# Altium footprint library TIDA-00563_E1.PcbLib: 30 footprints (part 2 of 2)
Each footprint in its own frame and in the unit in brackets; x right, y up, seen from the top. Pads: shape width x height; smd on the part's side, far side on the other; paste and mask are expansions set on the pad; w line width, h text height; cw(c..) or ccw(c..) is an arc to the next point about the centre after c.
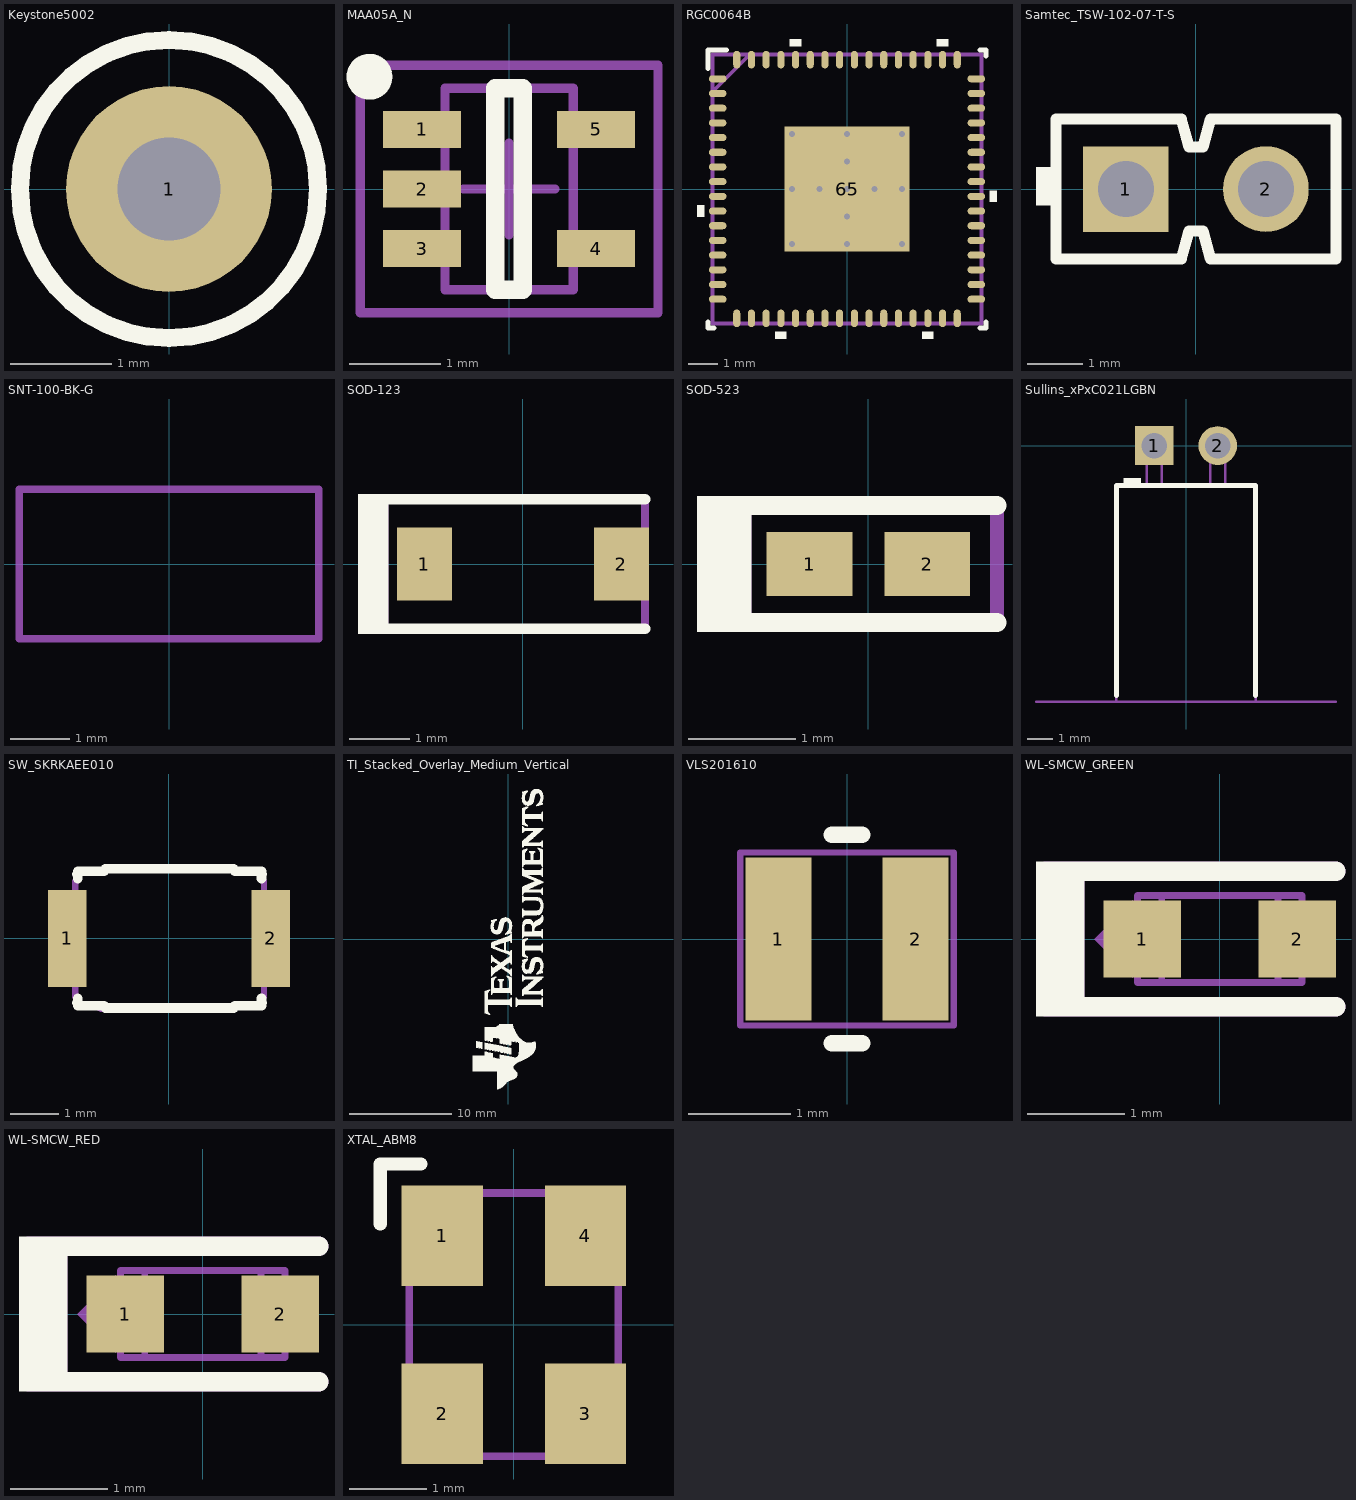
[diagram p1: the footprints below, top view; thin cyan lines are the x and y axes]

## Keystone5002 [mil] "For Keystone 500x miniature loop terminals"
height 181.1
pads (1):
  round 80 hole 40: 1(0,0)
Top Overlay:
  circle w7: c0,0 r58
Mechanical 5:
  circle w5: c0,0 r58.31
  text ".Designator" at -45,-10 h25
3D body: height 181.97, standoff -118.11, extent -49,-49 49.04,49.23

## MAA05A_N [mm] "SOT353, 5-Leads, Body 2x1.3mm, Pitch 0.65mm, Lead Span 2.1mm, IPC Medium Density"
height 1.1
pads (5):
  rect 0.85x0.4 smd: 1(-0.95,0.65) 2(-0.95,0) 3(-0.95,-0.65) 4(0.95,-0.65) 5(0.95,0.65)
Top Overlay:
  circle w0.25: c-1.524,1.225 r0.125
  lines w0.2: -0.15,-1.1 -0.15,1.1 0.15,1.1 0.15,-1.1 -0.15,-1.1
Mechanical 5:
  lines w0.1: -0.7,-1.1 -0.7,1.1 0.7,1.1 0.7,-1.1 -0.7,-1.1
  text ".Designator" at 0.33,-0.432 h0.64
Mechanical 15:
  lines w0.1: -0.5,0 0.5,0 ; 0,-0.5 0,0.5 ; -1.625,-1.35 1.625,-1.35 1.625,1.35 -1.625,1.35 -1.625,-1.35
3D body: height 1.1, standoff 0, extent -0.7,-1.1 0.7,1.1

## RGC0064B [mm]
height 1
pads (65):
  oval 0.6x0.24 smd mask+0.07: 1(-4.4,3.75) 2(-4.4,3.25) 3(-4.4,2.75) 4(-4.4,2.25) 5(-4.4,1.75) 6(-4.4,1.25) 7(-4.4,0.75) 8(-4.4,0.25) 9(-4.4,-0.25) 10(-4.4,-0.75) 11(-4.4,-1.25) 12(-4.4,-1.75) 13(-4.4,-2.25) 14(-4.4,-2.75) 15(-4.4,-3.25) 16(-4.4,-3.75) 33(4.4,-3.75) 34(4.4,-3.25) 35(4.4,-2.75) 36(4.4,-2.25) 37(4.4,-1.75) 38(4.4,-1.25) 39(4.4,-0.75) 40(4.4,-0.25) 41(4.4,0.25) 42(4.4,0.75) 43(4.4,1.25) 44(4.4,1.75) 45(4.4,2.25) 46(4.4,2.75) 47(4.4,3.25) 48(4.4,3.75)
  oval 0.24x0.6 smd mask+0.07: 17(-3.751,-4.4) 18(-3.251,-4.4) 19(-2.751,-4.4) 20(-2.251,-4.4) 21(-1.75,-4.4) 22(-1.25,-4.4) 23(-0.75,-4.4) 24(-0.25,-4.4) 25(0.25,-4.4) 26(0.75,-4.4) 27(1.25,-4.4) 28(1.75,-4.4) 29(2.251,-4.4) 30(2.751,-4.4) 31(3.251,-4.4) 32(3.751,-4.4) 49(3.751,4.4) 50(3.251,4.4) 51(2.751,4.4) 52(2.251,4.4) 53(1.75,4.4) 54(1.25,4.4) 55(0.75,4.4) 56(0.25,4.4) 57(-0.25,4.4) 58(-0.75,4.4) 59(-1.25,4.4) 60(-1.75,4.4) 61(-2.251,4.4) 62(-2.751,4.4) 63(-3.251,4.4) 64(-3.751,4.4)
  rect 4.25x4.25 smd paste-2.112: 65(0,0)
via -1.875,1.875 diameter 0.5 hole 0.2
via 0,1.875 diameter 0.5 hole 0.2
via 1.875,1.875 diameter 0.5 hole 0.2
via 0,0.937 diameter 0.5 hole 0.2
via -1.875,0 diameter 0.5 hole 0.2
via -0.937,0 diameter 0.5 hole 0.2
via 0,0 diameter 0.5 hole 0.2
via 0.937,0 diameter 0.5 hole 0.2
via 1.875,0 diameter 0.5 hole 0.2
via 0,-0.937 diameter 0.5 hole 0.2
via -1.875,-1.875 diameter 0.5 hole 0.2
via 0,-1.875 diameter 0.5 hole 0.2
via 1.875,-1.875 diameter 0.5 hole 0.2
Top Overlay:
  region: -4.849,-0.56 -5.103,-0.56 -5.103,-0.941 -4.849,-0.941
  region: -2.06,-4.849 -2.441,-4.849 -2.441,-5.103 -2.06,-5.103
  region: 2.941,-4.849 2.56,-4.849 2.56,-5.103 2.941,-5.103
  region: 4.849,-0.059 5.103,-0.059 5.103,-0.44 4.849,-0.44
  region: 3.441,4.849 3.06,4.849 3.06,5.103 3.441,5.103
  region: -1.56,4.849 -1.941,4.849 -1.941,5.103 -1.56,5.103
  lines w0.178: -4.725,-4.525 -4.725,-4.725 -4.525,-4.725 ; -4.725,4.096 -4.725,4.725 -4.097,4.725 ; 4.525,-4.725 4.725,-4.725 4.725,-4.525 ; 4.525,4.725 4.725,4.725 4.725,4.525
Top Paste:
  rectangle: 0.1,-1.888 1.888,-0.1
  region: -0.1,-0.1 -1.888,-0.1 -1.888,-1.888 -0.1,-1.888
  region: -0.1,1.888 -1.888,1.888 -1.888,0.1 -0.1,0.1
  rectangle: 0.1,0.1 1.888,1.888
Mechanical 5:
  lines w0.127: -4.575,3.305 -3.305,4.575 ; -4.575,-4.575 4.575,-4.575 4.575,4.575 -4.575,4.575 -4.575,-4.575 ; -4.575,-3.9 -4.575,-3.6 -4.575,-3.9 ; -4.575,-3.4 -4.575,-3.1 -4.575,-3.4 ; -4.575,-2.9 -4.575,-2.6 -4.575,-2.9 ; -4.575,-2.4 -4.575,-2.1 -4.575,-2.4 ; -4.575,-1.9 -4.575,-1.6 -4.575,-1.9 ; -4.575,-1.4 -4.575,-1.1 -4.575,-1.4 ; -4.575,-0.9 -4.575,-0.6 -4.575,-0.9 ; -4.575,-0.4 -4.575,-0.1 -4.575,-0.4 ; -4.575,0.1 -4.575,0.4 -4.575,0.1 ; -4.575,0.6 -4.575,0.9 -4.575,0.6 ; -4.575,1.1 -4.575,1.4 -4.575,1.1 ; -4.575,1.6 -4.575,1.9 -4.575,1.6 ; -4.575,2.1 -4.575,2.4 -4.575,2.1 ; -4.575,2.6 -4.575,2.9 -4.575,2.6 ; -4.575,3.1 -4.575,3.4 -4.575,3.1 ; -4.575,3.6 -4.575,3.9 -4.575,3.6 ; -3.9,-4.575 -3.6,-4.575 -3.9,-4.575 ; -3.9,4.575 -3.6,4.575 -3.9,4.575 ; -3.4,-4.575 -3.1,-4.575 -3.4,-4.575 ; -3.4,4.575 -3.1,4.575 -3.4,4.575 ; -2.9,-4.575 -2.6,-4.575 -2.9,-4.575 ; -2.9,4.575 -2.6,4.575 -2.9,4.575 ; -2.4,-4.575 -2.1,-4.575 -2.4,-4.575 ; -2.4,4.575 -2.1,4.575 -2.4,4.575 ; -1.9,-4.575 -1.6,-4.575 -1.9,-4.575 ; -1.9,4.575 -1.6,4.575 -1.9,4.575 ; -1.4,-4.575 -1.1,-4.575 -1.4,-4.575 ; -1.4,4.575 -1.1,4.575 -1.4,4.575 ; -0.9,-4.575 -0.6,-4.575 -0.9,-4.575 ; -0.9,4.575 -0.6,4.575 -0.9,4.575 ; -0.4,-4.575 -0.1,-4.575 -0.4,-4.575 ; -0.4,4.575 -0.1,4.575 -0.4,4.575 ; 0.1,-4.575 0.4,-4.575 0.1,-4.575 ; 0.1,4.575 0.4,4.575 0.1,4.575 ; 0.6,-4.575 0.9,-4.575 0.6,-4.575 ; 0.6,4.575 0.9,4.575 0.6,4.575 ; 1.1,-4.575 1.4,-4.575 1.1,-4.575 ; 1.1,4.575 1.4,4.575 1.1,4.575 ; 1.6,-4.575 1.9,-4.575 1.6,-4.575 ; 1.6,4.575 1.9,4.575 1.6,4.575 ; 2.1,-4.575 2.4,-4.575 2.1,-4.575 ; 2.1,4.575 2.4,4.575 2.1,4.575 ; 2.6,-4.575 2.9,-4.575 2.6,-4.575 ; 2.6,4.575 2.9,4.575 2.6,4.575 ; 3.1,-4.575 3.4,-4.575 3.1,-4.575 ; 3.1,4.575 3.4,4.575 3.1,4.575 ; 3.6,-4.575 3.9,-4.575 3.6,-4.575 ; 3.6,4.575 3.9,4.575 3.6,4.575 ; 4.575,-3.9 4.575,-3.6 4.575,-3.9 ; 4.575,-3.4 4.575,-3.1 4.575,-3.4 ; 4.575,-2.9 4.575,-2.6 4.575,-2.9 ; 4.575,-2.4 4.575,-2.1 4.575,-2.4 ; 4.575,-1.9 4.575,-1.6 4.575,-1.9 ; 4.575,-1.4 4.575,-1.1 4.575,-1.4 ; 4.575,-0.9 4.575,-0.6 4.575,-0.9 ; 4.575,-0.4 4.575,-0.1 4.575,-0.4 ; 4.575,0.1 4.575,0.4 4.575,0.1 ; 4.575,0.6 4.575,0.9 4.575,0.6 ; 4.575,1.1 4.575,1.4 4.575,1.1 ; 4.575,1.6 4.575,1.9 4.575,1.6 ; 4.575,2.1 4.575,2.4 4.575,2.1 ; 4.575,2.6 4.575,2.9 4.575,2.6 ; 4.575,3.1 4.575,3.4 4.575,3.1 ; 4.575,3.6 4.575,3.9 4.575,3.6
  text ".Designator" at -0.711,-0.356 h0.64
3D body: height 1, standoff 0, extent -4.574,-4.574 4.574,4.574
3D body: height 1.01, standoff 1, extent -3.875,3.11 -3.084,3.901

## Samtec_TSW-102-07-T-S [mm] "Header, 2.54 mm, 2x1, Tin, TH"
height 8.382
pads (2):
  rect 1.55x1.55 hole 1.02: 1(-1.27,0)
  round 1.55 hole 1.02: 2(1.27,0)
Top Overlay:
  rectangle: -2.9,-0.3 -2.54,0.4
  lines w0.2: -2.54,-1.27 -0.264,-1.27 -0.127,-0.762 0,-0.762 0.127,-0.762 0.264,-1.27 2.54,-1.27 2.54,1.27 0.264,1.27 0.127,0.762 0,0.762 -0.127,0.762 -0.264,1.27 -2.54,1.27 -2.54,-1.27
Mechanical 5:
  lines w0.1: -2.54,-1.27 -2.54,1.27 -0.264,1.27 -0.127,0.762 0,0.762 0.127,0.762 0.264,1.27 2.54,1.27 2.54,-1.27 0.264,-1.27 0.127,-0.762 0,-0.762 -0.127,-0.762 -0.264,-1.27 -2.54,-1.27
  text ".Designator" at 0.686,0.356 h0.64
3D body: height 8.38, standoff -2.54, extent -2.54,-1.27 2.54,1.27

## SNT-100-BK-G [mil] "Samtec STEP model"
height 345
pads (1):
  round 1 on Mech3: 0(0,0)
Mechanical 5:
  lines w5: -100,-50 -100,50 100,50 100,-50 -100,-50
3D body: height 344, standoff 104, extent -100,-50.05 100,50.05

## SOD-123 [mm] "On Semi recommended land pattern"
height 1.35
pads (2):
  rect 0.915x1.22 smd: 1(-1.637,0) 2(1.637,0)
Top Overlay:
  rectangle: -2.743,-1.168 -2.235,1.168
  lines w0.178: -2.413,-1.079 2.032,-1.079 ; -2.413,1.079 2.032,1.079
Mechanical 5:
  rectangle: -2.743,-1.168 -2.235,1.168
  lines w0.127: -2.413,-1.079 2.032,-1.079 2.032,1.079 -2.413,1.079
  text ".Designator" at 0.356,0.356 h0.64
3D body: height 1.35, standoff 0, extent -1.932,-0.9 1.932,0.9

## SOD-523 [mm] "NXP Semiconductor recommended land pattern, nominal STEP model"
height 0.7
pads (2):
  rect 0.8x0.6 smd paste+0: 1(-0.55,0) 2(0.55,0)
Top Overlay:
  rectangle: -1.6,-0.635 -1.092,0.635
  lines w0.178: -1.475,-0.546 0,-0.546 1.2,-0.546 ; -1.475,0.546 0,0.546 1.2,0.546
Mechanical 5:
  rectangle: -1.6,-0.635 -1.092,0.635
  lines w0.127: -1.475,-0.546 0,-0.546 1.2,-0.546 1.2,0.546 0,0.546 -1.475,0.546
  text ".Designator" at -0.66,-0.381 h0.64
3D body: height 0.72, standoff 0.02, extent -0.8,-0.399 0.8,0.399

## Sullins_xPxC021LGBN [mm] "Receptacle, 2.54 mm, 2x1, R/A, SMT"
height 2.74
pads (2):
  rect 1.55x1.55 hole 1.02: 1(-1.27,0)
  round 1.55 hole 1.02: 2(1.27,0)
Top Overlay:
  rectangle: -2.5,-1.6 -1.8,-1.3
  lines w0.2: -2.79,-10 -2.79,-1.6 2.79,-1.6 2.79,-10
Mechanical 1:
  lines w0.1: -6,-10.25 6,-10.25
Mechanical 5:
  lines w0.1: -1.57,-1.6 -1.57,0.2 -0.97,0.2 -0.97,-1.6 ; 0.97,-1.6 0.97,0.2 1.57,0.2 1.57,-1.6 ; -2.79,-10.25 2.79,-10.25 2.79,-1.6 -2.79,-1.6 -2.79,-10.25
  text ".Designator" at -1.067,-6.147 h0.64
3D body: height 1.47, standoff 1.07, extent 0.971,-1.599 1.569,0.199
3D body: height 1.47, standoff 1.07, extent -1.569,-1.599 -0.971,0.199
3D body: height 2.74, standoff 0, extent -2.789,-10.249 2.789,-1.601
3D body: height 1.27, standoff -4.42, extent -1.57,-0.199 -0.971,0.199
3D body: height 1.27, standoff -4.42, extent 0.971,-0.199 1.569,0.199

## SW_SKRKAEE010 [mm] "Alps recommended land pattern"
height 2
pads (2):
  rect 0.8x2 smd: 1(-2.1,0) 2(2.1,0)
Top Overlay:
  lines w0.2: -1.9,-1.326 -1.888,-1.324 ; -1.9,1.326 -1.888,1.324 ; -1.888,-1.239 -1.888,-1.389 -1.338,-1.389 ; -1.888,1.239 -1.888,1.389 -1.338,1.389 ; -1.313,-1.439 1.337,-1.439 ; -1.313,1.439 1.337,1.439 ; 1.362,-1.389 1.912,-1.389 1.912,-1.239 ; 1.362,1.389 1.912,1.389 1.912,1.239 ; 1.912,-1.324 1.924,-1.326 ; 1.912,1.324 1.924,1.326
Mechanical 5:
  lines w0.127: -1.938,-1.211 -1.938,-0.811 -1.938,-0.394 ; -1.938,-0.711 -2.388,-0.711 -2.388,0.689 -1.938,0.689 ; -1.938,-0.336 -1.938,0.314 -1.938,0.372 -1.938,0.789 -1.938,1.189 ; -1.924,-1.211 -1.9,-1.348 -1.888,-1.346 ; -1.924,1.189 -1.9,1.326 -1.888,1.324 ; -1.888,-1.211 -1.888,-1.261 -1.888,-1.411 -1.338,-1.411 ; -1.888,1.189 -1.888,1.239 -1.888,1.389 -1.338,1.389 ; -1.481,-1.411 -1.462,-1.425 ccw(c-1.347,-1.261) -1.347,-1.461 ; -1.313,-1.461 1.337,-1.461 ; -1.313,1.439 1.337,1.439 ; 1.362,-1.411 1.912,-1.411 1.912,-1.261 ; 1.362,1.389 1.912,1.389 1.912,1.239 ; 1.912,-1.346 1.924,-1.348 1.949,-1.211 ; 1.912,1.324 1.924,1.326 1.949,1.189 ; 1.962,-1.211 1.962,-0.811 1.962,-0.394 ; 1.962,-0.711 2.412,-0.711 2.412,0.689 1.962,0.689 ; 1.962,-0.336 1.962,0.314 ; 1.962,0.372 1.962,0.789 1.962,1.189
  text ".Designator" at 0.254,-0.686 h0.64
3D body: height 1.96, standoff -0.04, extent -2.4,-1.45 2.4,1.45

## TI_Stacked_Overlay_Medium_Vertical [mm]
Top Overlay:
  drawing of 18 lines, arcs and shapes, not listed

## VLS201610 [mm] "TDK"
height 0.95
pads (2):
  rect 0.65x1.6 smd: 1(-0.675,0) 2(0.675,0)
Top Overlay:
  lines w0.165: -0.15,-1.025 0.15,-1.025 ; -0.15,1.025 0.15,1.025
Mechanical 5:
  lines w0.06: -1.05,-0.85 1.05,-0.85 1.05,0.85 -1.05,0.85 -1.05,-0.85
  text ".Designator" at -0.508,-0.381 h0.64
3D body: height 0.95, standoff 0, extent -1.049,-0.849 1.049,0.849

## WL-SMCW_GREEN [mm] "WURTH"
height 0.8
pads (2):
  rect 0.8x0.8 smd: 1(-0.8,0) 2(0.8,0)
Top Overlay:
  rectangle: -1.9,-0.8 -1.4,0.8
  lines w0.2: -1.6,-0.7 1.2,-0.7 ; -1.6,0.7 1.2,0.7
Mechanical 5:
  region: -0.9,-0.4 -0.9,0.4 -1.3,0
  lines w0.2: -1.65,-0.7 -1.65,0.55 ; 1.2,-0.7 -1.5,-0.7 ; 1.2,0.7 -1.5,0.7 ; -1.5,-0.7 -1.5,0.7 ; -1.5,-0.7 -1.8,-0.7 -1.8,0.7 -1.5,0.7
  text ".Designator" at -0.559,-0.406 h0.64
Mechanical 13:
  lines w0.07: -0.6,-0.45 -0.6,0.45 ; 0.6,-0.45 0.6,0.45 ; -0.85,-0.45 -0.85,0.45 0.85,0.45 0.85,-0.45 -0.85,-0.45
3D body: height 0.35, standoff 0, extent -0.849,-0.449 -0.601,0.449
3D body: height 0.35, standoff 0, extent -0.599,-0.449 0.599,0.449
3D body: height 0.35, standoff 0, extent 0.601,-0.449 0.849,0.449
3D body: height 0.8, standoff 0.35, extent -0.599,-0.449 0.599,0.449
3D body: height 0.36, standoff 0.35, extent -0.599,-0.449 0.599,0.449

## WL-SMCW_RED [mm] "WURTH"
height 0.8
pads (2):
  rect 0.8x0.8 smd: 1(-0.8,0) 2(0.8,0)
Top Overlay:
  rectangle: -1.9,-0.8 -1.4,0.8
  lines w0.2: -1.6,-0.7 1.2,-0.7 ; -1.6,0.7 1.2,0.7
Mechanical 5:
  region: -0.9,-0.4 -0.9,0.4 -1.3,0
  lines w0.2: -1.65,-0.7 -1.65,0.55 ; 1.2,-0.7 -1.5,-0.7 ; 1.2,0.7 -1.5,0.7 ; -1.5,-0.7 -1.8,-0.7 -1.8,0.7 -1.5,0.7 ; -1.5,-0.7 -1.5,0.7
  text ".Designator" at -0.406,-0.406 h0.64
Mechanical 13:
  lines w0.07: -0.6,-0.45 -0.6,0.45 ; 0.6,-0.45 0.6,0.45 ; -0.85,-0.45 0.85,-0.45 0.85,0.45 -0.85,0.45 -0.85,-0.45
3D body: height 0.36, standoff 0.35, extent -0.599,-0.449 0.599,0.449
3D body: height 0.8, standoff 0.35, extent -0.599,-0.449 0.599,0.449
3D body: height 0.35, standoff 0, extent 0.601,-0.449 0.849,0.449
3D body: height 0.35, standoff 0, extent -0.599,-0.449 0.599,0.449
3D body: height 0.35, standoff 0, extent -0.849,-0.449 -0.601,0.449

## XTAL_ABM8 [mm] "Abracon recommended land pattern"
height 0.8
pads (4):
  rect 1.05x1.3 smd: 1(-0.925,1.15) 2(-0.925,-1.15) 3(0.925,-1.15) 4(0.925,1.15)
Top Overlay:
  lines w0.17: -1.725,1.3 -1.725,2.075 -1.2,2.075
Mechanical 5:
  circle w0.1: c-0.827,1.2 r0.2
  lines w0.1: -1.35,-1.7 1.35,-1.7 1.35,1.7 -1.35,1.7 -1.35,-1.7
  text ".Designator" at 0.61,0.229 h0.64
3D body: height 0.79, standoff 0, extent -1.349,-1.699 1.349,1.699
3D body: height 0.8, standoff 0.79, extent -1.349,-1.699 1.349,1.699
3D body: height 0.8, standoff 0.5, extent -0.964,1.063 -0.69,1.337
